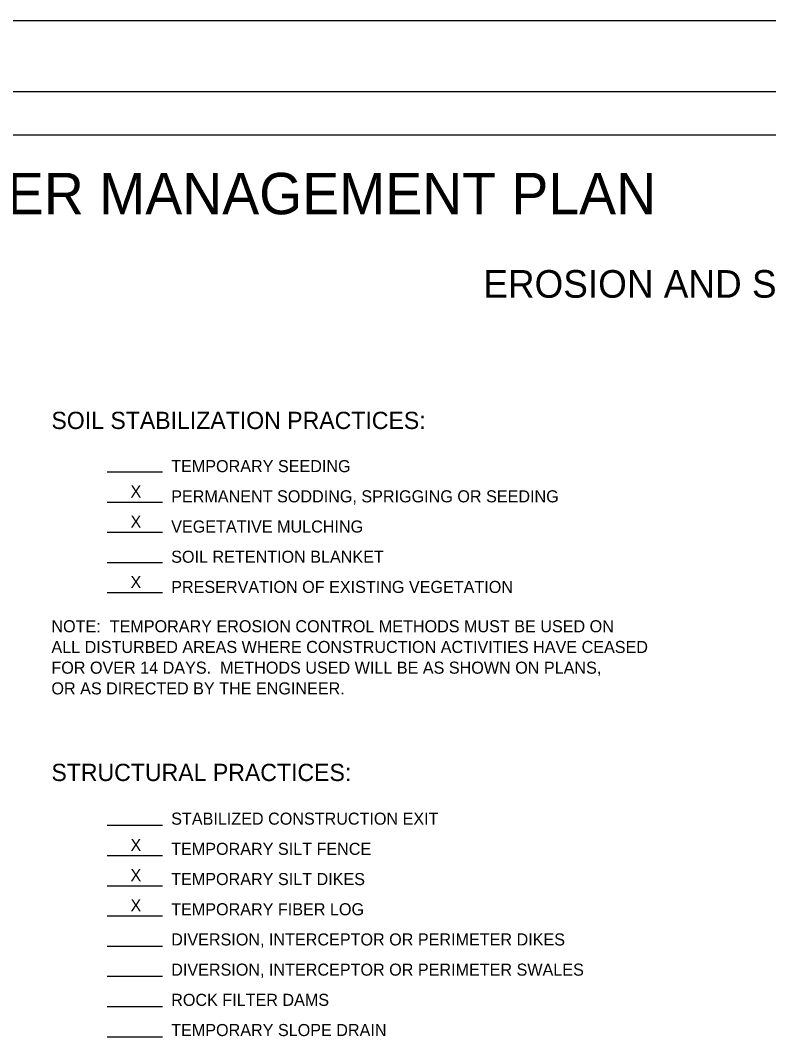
# Model space of a CAD drawing. Extents: x 1975980 to 1976688, y 470504 to 470744.
# Drawn here: x 1976479.8 to 1976566.5, y 470625.7 to 470744.2 of the extents above; entities that cross this region are included whole.
import ezdxf

# ---------------------------------------------------------------- set-up
doc = ezdxf.new("R2010")
doc.units = 0
for name, color, linetype in [('SHT_Plot_Shape_Full', 7, 'Continuous'), ('SHT_Plot_Shape_Half', 7, 'Continuous'), ('SHT_Sheet_Border', 7, 'Continuous')]:
    doc.layers.add(name, color=color, linetype=linetype)

msp = doc.modelspace()

# ---------------------------------------------------------------- linework, layer by layer
for p, q in [((1976496.25, 470691.84), (1976489.81, 470691.84)), ((1976496.25, 470688.34), (1976489.81, 470688.34)), ((1976496.25, 470684.84), (1976489.81, 470684.84)), ((1976496.25, 470681.34), (1976489.81, 470681.34)), ((1976496.25, 470677.84), (1976489.81, 470677.84)), ((1976496.25, 470650.87), (1976489.81, 470650.87)), ((1976496.25, 470647.37), (1976489.81, 470647.37)), ((1976496.25, 470643.87), (1976489.81, 470643.87)), ((1976496.25, 470640.37), (1976489.81, 470640.37)), ((1976496.25, 470636.87), (1976489.81, 470636.87)), ((1976496.25, 470633.37), (1976489.81, 470633.37)), ((1976496.25, 470629.87), (1976489.81, 470629.87)), ((1976496.25, 470626.37), (1976489.81, 470626.37))]:
    msp.add_line(p, q)
at = {"layer": 'SHT_Plot_Shape_Full'}
msp.add_lwpolyline([(1976327.98, 470744.2), (1976687.98, 470744.2), (1976687.98, 470504.2), (1976327.98, 470504.2)], close=True, dxfattribs=at)
at = {"layer": 'SHT_Plot_Shape_Half'}
msp.add_lwpolyline([(1976344.35, 470735.95), (1976684.35, 470735.95), (1976684.35, 470515.95), (1976344.35, 470515.95)], close=True, dxfattribs=at)
at = {"layer": 'SHT_Sheet_Border'}
msp.add_lwpolyline([(1976678.85, 470520.95), (1976363.85, 470520.95), (1976363.85, 470730.95), (1976678.85, 470730.95)], close=True, dxfattribs=at)

# ---------------------------------------------------------------- texts
for s, height, p in [('STORM WATER MANAGEMENT PLAN', 4.8011, (1976438.97, 470721.73)), ('EROSION AND SEDIMENT CONTROLS', 3.2007, (1976533.44, 470712.06)), ('SOIL STABILIZATION PRACTICES:', 2, (1976483.36, 470696.84)), ('TEMPORARY SEEDING', 1.4, (1976497.25, 470691.84)), ('X', 1.4, (1976492.53, 470688.9)), ('PERMANENT SODDING, SPRIGGING OR SEEDING', 1.4, (1976497.25, 470688.34)), ('X', 1.4, (1976492.53, 470685.4)), ('VEGETATIVE MULCHING', 1.4, (1976497.25, 470684.84)), ('SOIL RETENTION BLANKET', 1.4, (1976497.25, 470681.34)), ('X', 1.4, (1976492.53, 470678.4)), ('PRESERVATION OF EXISTING VEGETATION', 1.4, (1976497.25, 470677.84)), ('NOTE:  TEMPORARY EROSION CONTROL METHODS MUST BE USED ON', 1.4, (1976483.36, 470673.28)), ('ALL DISTURBED AREAS WHERE CONSTRUCTION ACTIVITIES HAVE CEASED', 1.4, (1976483.36, 470670.88)), ('FOR OVER 14 DAYS.  METHODS USED WILL BE AS SHOWN ON PLANS,', 1.4, (1976483.36, 470668.48)), ('OR AS DIRECTED BY THE ENGINEER.', 1.4, (1976483.36, 470666.08)), ('STRUCTURAL PRACTICES:', 2, (1976483.36, 470656.04)), ('STABILIZED CONSTRUCTION EXIT', 1.4, (1976497.25, 470650.98)), ('X', 1.4, (1976492.53, 470647.93)), ('TEMPORARY SILT FENCE', 1.4, (1976497.25, 470647.48)), ('X', 1.4, (1976492.53, 470644.43)), ('TEMPORARY SILT DIKES', 1.4, (1976497.25, 470643.98)), ('X', 1.4, (1976492.53, 470640.93)), ('TEMPORARY FIBER LOG', 1.4, (1976497.25, 470640.48)), ('DIVERSION, INTERCEPTOR OR PERIMETER DIKES', 1.4, (1976497.25, 470636.98)), ('DIVERSION, INTERCEPTOR OR PERIMETER SWALES', 1.4, (1976497.25, 470633.48)), ('ROCK FILTER DAMS', 1.4, (1976497.25, 470629.98)), ('TEMPORARY SLOPE DRAIN', 1.4, (1976497.25, 470626.48))]:
    msp.add_text(s, height=height).set_placement(p)

doc.saveas('drawing.dxf')
